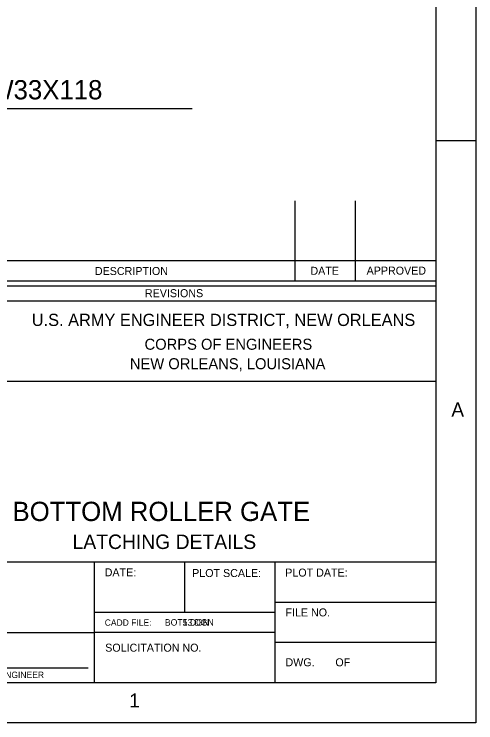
# Model space of a CAD drawing. Extents: x 18232 to 22378, y 12454 to 22381.
# Drawn here: x 22375.371 to 22376.33, y 22369.663 to 22371.133 of the extents above; entities that cross this region are included whole.
import ezdxf

# ---------------------------------------------------------------- set-up
doc = ezdxf.new("R2010")
doc.units = 0
for name, color, linetype in [('Level 1', 7, 'Continuous'), ('Level 2', 7, 'Continuous'), ('Level 3', 7, 'Continuous')]:
    doc.layers.add(name, color=color, linetype=linetype)

msp = doc.modelspace()

# ---------------------------------------------------------------- linework, layer by layer
at = {"layer": 'Level 1'}
for p, q in [((22376.2463, 22370.8713), (22376.3297, 22370.8713)), ((22375.9547, 22370.5797), (22375.9547, 22370.7463)), ((22376.0797, 22370.5797), (22376.0797, 22370.7463)), ((22376.2463, 22370.6213), (22375.163, 22370.6213)), ((22376.2463, 22370.5797), (22375.163, 22370.5797)), ((22376.2463, 22370.5692), (22375.163, 22370.5692)), ((22376.2463, 22370.538), (22375.163, 22370.538)), ((22376.2463, 22370.3713), (22375.163, 22370.3713)), ((22376.2463, 22369.9963), (22375.163, 22369.9963)), ((22375.538, 22369.7463), (22375.538, 22369.9963)), ((22375.7255, 22369.8922), (22375.7255, 22369.9963)), ((22375.913, 22369.7463), (22375.913, 22369.9963)), ((22376.2463, 22369.913), (22375.913, 22369.913)), ((22375.913, 22369.8922), (22375.538, 22369.8922)), ((22375.163, 22369.8505), (22375.538, 22369.8505)), ((22375.913, 22369.8505), (22375.538, 22369.8505)), ((22376.2463, 22369.8297), (22375.913, 22369.8297)), ((22375.1742, 22369.7769), (22375.5247, 22369.7769))]:
    msp.add_line(p, q, dxfattribs=at)
for points in [[(22369.663, 22374.3297), (22376.3297, 22374.3297), (22376.3297, 22369.663), (22369.663, 22369.663)], [(22369.913, 22374.2463), (22376.2463, 22374.2463), (22376.2463, 22369.7463), (22369.913, 22369.7463)]]:
    msp.add_lwpolyline(points, close=True, dxfattribs=at)
at = {"layer": 'Level 3'}
msp.add_line((22374.456, 22370.938), (22375.7408, 22370.938), dxfattribs=at)

# ---------------------------------------------------------------- texts
at = {"layer": 'Level 1'}
for s, height, p in [('DESCRIPTION', 0.016604, (22375.5387, 22370.5922)), ('DATE', 0.0166, (22375.9862, 22370.5926)), ('APPROVED', 0.0166, (22376.1029, 22370.593)), ('REVISIONS', 0.0166, (22375.6426, 22370.5462)), ('U.S. ARMY ENGINEER DISTRICT, NEW ORLEANS', 0.025396, (22375.4076, 22370.4864)), ('CORPS OF ENGINEERS', 0.022856, (22375.6418, 22370.4371)), ('NEW ORLEANS, LOUISIANA', 0.022856, (22375.6113, 22370.3967)), ('A', 0.0292, (22376.279, 22370.2986)), ('DATE:', 0.0166, (22375.559, 22369.9669)), ('PLOT SCALE:', 0.016604, (22375.7406, 22369.9655)), ('PLOT DATE:', 0.0166, (22375.9339, 22369.9664)), ('FILE NO.', 0.0166, (22375.9344, 22369.8838)), ('CADD FILE:', 0.01321, (22375.5591, 22369.8644)), ('SOLICITATION NO.', 0.016604, (22375.5601, 22369.8106)), ('DWG.       OF', 0.016604, (22375.9344, 22369.7803)), ('DESIGN ENGINEER', 0.013208, (22375.2682, 22369.7559)), ('1', 0.0292, (22375.6101, 22369.6948))]:
    msp.add_text(s, height=height, dxfattribs=at).set_placement(p)
at = {"layer": 'Level 2'}
for s, height, p in [('BOTTOM ROLLER GATE', 0.04, (22375.3675, 22370.0817)), ('LATCHING DETAILS', 0.03, (22375.4923, 22370.0237)), ('BOT5.DGN', 0.0134, (22375.684, 22369.8647)), ('BOT13.DGN', 0.0134, (22375.684, 22369.8647))]:
    msp.add_text(s, height=height, dxfattribs=at).set_placement(p)
at = {"layer": 'Level 3'}
msp.add_text('PLAN AT END OF GATE BELOW W33X118', height=0.04, dxfattribs=at).set_placement((22374.4961, 22370.9566))

doc.saveas('drawing.dxf')
